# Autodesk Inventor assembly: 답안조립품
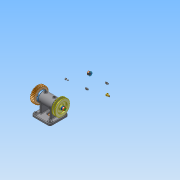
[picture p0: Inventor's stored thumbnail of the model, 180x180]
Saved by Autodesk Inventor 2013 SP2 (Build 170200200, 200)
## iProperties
Created: 2025-10
Part Number: 답안조립품
Document SubType Name: Assembly
Designer: a
Author: a
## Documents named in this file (17)
- C:\Users\a\Desktop\751003V1014\답안조립품.iam
- C:\Users\a\Desktop\751003V1014\6각 구멍붙이 볼트 M4x10.ipt
- C:\Users\a\Desktop\751003V1014\6각 너트 M8x1.ipt
- C:\Users\a\Desktop\751003V1014\6각 머리 볼트 M6x0.75x8.ipt
- C:\Users\a\Desktop\751003V1014\V 벨트 풀리.ipt
- C:\Users\a\Desktop\751003V1014\가스켓.ipt
- C:\Users\a\Desktop\751003V1014\그리스 니플 M6x0.75.ipt
- C:\Users\a\Desktop\751003V1014\깊은 홈 볼 베어링 6002.ipt
- C:\Users\a\Desktop\751003V1014\본체.ipt
- C:\Users\a\Desktop\751003V1014\스퍼 기어.ipt
- C:\Users\a\Desktop\751003V1014\스프링 와셔 M8.ipt
- C:\Users\a\Desktop\751003V1014\실링.ipt
- C:\Users\a\Desktop\751003V1014\오일 실 15 25 4.ipt
- C:\Users\a\Desktop\751003V1014\축.ipt
- C:\Users\a\Desktop\751003V1014\커버.ipt
- C:\Users\a\Desktop\751003V1014\평 와셔 M8.ipt
- C:\Users\a\Desktop\751003V1014\평행 키 3x3x12.ipt
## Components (10 placed, 6 different names)
1. 6각 구멍붙이 볼트 M4x10:1
2. 6각 너트 M8x1:1
3. 6각 머리 볼트 M6x0.75x8:1
4. V 벨트 풀리:1
5. 가스켓:1
6. 그리스 니플 M6x0.75:1
7. 가스켓:2
8. 6각 구멍붙이 볼트 M4x10:2
9. 6각 너트 M8x1:2
10. 그리스 니플 M6x0.75:2
